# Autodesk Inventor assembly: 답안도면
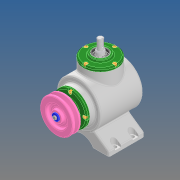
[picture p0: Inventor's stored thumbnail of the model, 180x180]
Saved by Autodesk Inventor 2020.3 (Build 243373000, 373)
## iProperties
Created: 2021-04
Part Number: 답안도면
Document SubType Name: Assembly
Designer: EZDESIGN
Author: EZDESIGN
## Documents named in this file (17)
- C:\Users\EZDESIGN\Desktop\710407V1005\답안도면.iam
- C:\Users\EZDESIGN\Desktop\710407V1005\키 5 x 5 x 14.ipt
- C:\Users\EZDESIGN\Desktop\710407V1005\키 4 x 4 x 14.ipt
- C:\Users\EZDESIGN\Desktop\710407V1005\커버.ipt
- C:\Users\EZDESIGN\Desktop\710407V1005\육각볼트 M4 x 8.ipt
- C:\Users\EZDESIGN\Desktop\710407V1005\와셔 4 x 16.ipt
- C:\Users\EZDESIGN\Desktop\710407V1005\오일실 17 x 32 x 8.ipt
- C:\Users\EZDESIGN\Desktop\710407V1005\서브 축.ipt
- 서브 축.ipt
- C:\Users\EZDESIGN\Desktop\710407V1005\서브 베벨기어.ipt
- C:\Users\EZDESIGN\Desktop\710407V1005\볼트 M4 x 10.ipt
- C:\Users\EZDESIGN\Desktop\710407V1005\본체.ipt
- C:\Users\EZDESIGN\Desktop\710407V1005\베어링 6203.ipt
- C:\Users\EZDESIGN\Desktop\710407V1005\메인 축.ipt
- 메인 축.ipt
- C:\Users\EZDESIGN\Desktop\710407V1005\메인 베벨기어.ipt
- C:\Users\EZDESIGN\Desktop\710407V1005\V-벨트풀리.ipt
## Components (1 placed, 1 different names)
1. V-벨트풀리:1
